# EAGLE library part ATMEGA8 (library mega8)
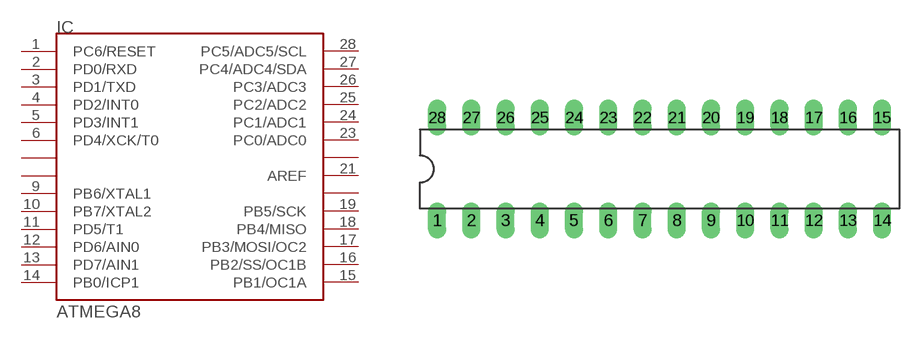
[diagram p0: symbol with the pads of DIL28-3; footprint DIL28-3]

Designator prefix IC

## ATMEGA8  [DIL28-3]
1  PC6/RESET
2  PD0/RXD
3  PD1/TXD
4  PD2/INT0
5  PD3/INT1
6  PD4/XCK/T0
7  PWR  pwr
8  GND  sup
9  PB6/XTAL1
10  PB7/XTAL2
11  PD5/T1
12  PD6/AIN0
13  PD7/AIN1
14  PB0/ICP1
15  PB1/OC1A
16  PB2/SS/OC1B
17  PB3/MOSI/OC2
18  PB4/MISO
19  PB5/SCK
20  AVCC  pwr
21  AREF
22  GN  sup
23  PC0/ADC0
24  PC1/ADC1
25  PC2/ADC2
26  PC3/ADC3
27  PC4/ADC4/SDA
28  PC5/ADC5/SCL

## Footprint DIL28-3 (pad centres in mm)
drill 0.813 long: 1 -17.02,-4; 2 -14.48,-4; 3 -11.94,-4; 4 -9.4,-4; 5 -6.86,-4; 6 -4.32,-4; 7 -1.78,-4; 8 0.76,-4; 9 3.3,-4; 10 5.84,-4; 11 8.38,-4; 12 10.92,-4; 13 13.46,-4; 14 16,-4; 15 16,3.62; 16 13.46,3.62; 17 10.92,3.62; 18 8.38,3.62; 19 5.84,3.62; 20 3.3,3.62; 21 0.76,3.62; 22 -1.78,3.62; 23 -4.32,3.62; 24 -6.86,3.62; 25 -9.4,3.62; 26 -11.94,3.62; 27 -14.48,3.62; 28 -17.02,3.62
